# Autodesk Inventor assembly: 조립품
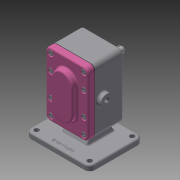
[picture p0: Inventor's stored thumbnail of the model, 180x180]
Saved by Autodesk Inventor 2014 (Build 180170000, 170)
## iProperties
Created: 2020-04
Part Number: 조립품
Document SubType Name: Assembly
Designer: kh
Author: kh
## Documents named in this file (11)
- C:\Users\kh\Desktop\700407V1014\조립품.iam
- C:\Users\kh\Desktop\700407V1014\본체.ipt
- C:\Users\kh\Desktop\700407V1014\개스킷.ipt
- C:\Users\kh\Desktop\700407V1014\메인축.ipt
- C:\Users\kh\Desktop\700407V1014\베어링부시.ipt
- C:\Users\kh\Desktop\700407V1014\볼트 M5.ipt
- C:\Users\kh\Desktop\700407V1014\서브축.ipt
- C:\Users\kh\Desktop\700407V1014\스퍼기어.ipt
- C:\Users\kh\Desktop\700407V1014\오일 실 16 28 7.ipt
- C:\Users\kh\Desktop\700407V1014\커버.ipt
- C:\Users\kh\Desktop\700407V1014\키 6 x 6 x 18.ipt
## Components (1 placed, 1 different names)
1. 개스킷:1
## Component patterns: 구성요소 패턴 2:2 (2 elements), 구성요소 패턴 1:2 (2 elements), 구성요소 패턴 1:3 (2 elements), 구성요소 패턴 1:4 (2 elements)
